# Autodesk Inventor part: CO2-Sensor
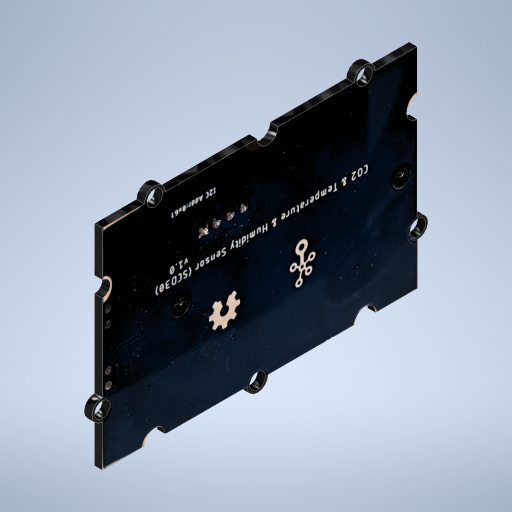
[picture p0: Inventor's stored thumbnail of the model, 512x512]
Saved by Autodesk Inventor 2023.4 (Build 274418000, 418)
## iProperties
Created: 2022-12
Part Number: CO2-Sensor
Material: Générique
Document SubType Name: Modeling
Designer: ecuenot
Density: 1 g/cm^3
Appearance: Noir
Author: ecuenot
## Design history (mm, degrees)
sketch "Esquisse1"
  geometry: L1 (8.143, -20)-(0.048, -20); L2 (8.048, 40.094)-(0.048, 40.094); L3 (40.048, -19.906)-(32.048, -19.906); L4 (28.048, -19.906)-(11.948, -19.906); L5 (40.048, -11.906)-(40.048, -19.906); L6 (40.048, 6.594)-(40.048, -7.906); L7 (40.048, 40.094)-(40.048, 32.094); L8 (40.048, 28.094)-(40.048, 10.594); L9 (40.048, 40.094)-(31.495, 40.094); L10 (28.495, 40.094)-(12.048, 40.094); L11 (0.048, 40.094)-(0.048, 32.094); L12 (0.048, 28.094)-(0.048, 12.5); L13 (0.048, 8.5)-(0.048, -8); L14 (0.048, -12)-(0.048, -20); C1 r 1.5 at (10.048, 40.094); C2 r 1.5 at (10.048, -20.07); C3 r 1.5 at (40.048, -9.906); C4 r 1.5 at (40.048, 30.094); C5 r 1.5 at (0.048, 10.5); A1 r 1.907 centre (10.048, -20.07) between (8.143, -20) and (11.948, -19.906); A2 r 2 centre (0.048, 10.5) between (0.048, 12.5) and (0.048, 8.5); A3 r 2 centre (40.048, 30.094) between (40.048, 28.094) and (40.048, 32.094); A4 r 2 centre (40.048, 8.594) between (40.048, 10.594) and (40.048, 6.594); A5 r 2 centre (40.048, -9.906) between (40.048, -11.906) and (40.048, -7.906); A6 r 1.5 centre (29.995, 40.094) between (28.495, 40.094) and (31.495, 40.094); A7 r 2 centre (30.048, -19.906) between (32.048, -19.906) and (28.048, -19.906); A8 r 2 centre (0.048, 30.094) between (0.048, 28.094) and (0.048, 32.094); A9 r 2 centre (0.048, -10) between (0.048, -12) and (0.048, -8); A10 r 2 centre (10.048, 40.094) between (12.048, 40.094) and (8.048, 40.094); 1 further point
  constraints: 28 end point, 20 point on circle, 18 perpendicular, 15 centre point, 5 coincident, 4 vertical, 3 horizontal
  dimensions: "d0" = 40 distance of L3.start L1.end; "d1" = 60 distance of L7.start L3.start; "d48" = 3 diameter of C1; "d246" = 4 diameter of A2; "d247" = 4 diameter of A3; "d248" = 4 diameter of A5; "d249" = 4 diameter of A10; "d250" = 4 diameter of A9; "d251" = 4 diameter of A8; "d252" = 4 diameter of A4; "d255" = 10 distance from line of L2 A8.centre; "d256" = 10 distance from line of L1 A9.centre; "d261" = 4 diameter of A7; "d262" = 3 diameter of C2; "d263" = 3 diameter of C3; "d264" = 3 diameter of C4; "d265" = 1.5 radius of A6; "d266" = 3 diameter of C5
extrude "Extrusion28" new body sketch "Esquisse1" distance "d267" = 1.5; taper "d268" = 0 deg
sketch "Esquisse37"
  geometry: L1 (19.906, 32.048)-(19.906, 40.048) reference; L2 (19.906, 40.048)-(19.707, -0.233); L3 (19.707, -0.233)-(-40.089, 0.062); L4 (-40.089, 0.062)-(-39.89, 40.343); L5 (-39.89, 40.343)-(19.906, 40.048); 1 further point; 1 other entity
  constraints: 2 other
feature "Décalcomanie5" sketch "Esquisse37"
sketch "Esquisse38"
  geometry: L1 (40.094, 40.048)-(40.094, 31.495) reference; L2 (-20, 0.048)-(-20, 8.143) reference; L3 (-20, 0.048)-(-20, 40.048); L4 (-20, 40.048)-(39.379, 40.048); L5 (39.379, 40.048)-(39.379, 0.048); L6 (39.379, 0.048)-(-20, 0.048); 1 further point; 1 other entity
  constraints: 2 other
feature "Décalcomanie7" sketch "Esquisse38"
node "Solide2"
node "Image11"
node "Image13"
other parameters: "d213" = 5, "d214" = 5
